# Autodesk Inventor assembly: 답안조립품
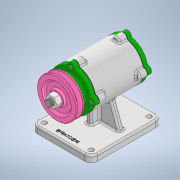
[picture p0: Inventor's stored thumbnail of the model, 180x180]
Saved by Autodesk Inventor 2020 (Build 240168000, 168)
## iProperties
Created: 2022-11
Part Number: 답안조립품
Document SubType Name: Assembly
Designer: owner
Author: owner
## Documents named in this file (12)
- C:\Users\owner\Desktop\721108V1016\답안조립품.iam
- C:\Users\owner\Desktop\721108V1016\본체.ipt
- C:\Users\owner\Desktop\721108V1016\V-벨트풀리.ipt
- C:\Users\owner\Desktop\721108V1016\개스킷.ipt
- C:\Users\owner\Desktop\721108V1016\너트 M12 x 1.25.ipt
- C:\Users\owner\Desktop\721108V1016\뒤커버.ipt
- C:\Users\owner\Desktop\721108V1016\베어링 6204.ipt
- C:\Users\owner\Desktop\721108V1016\볼트 M4 x 12.ipt
- C:\Users\owner\Desktop\721108V1016\앞커버.ipt
- C:\Users\owner\Desktop\721108V1016\오일 실.ipt
- C:\Users\owner\Desktop\721108V1016\축.ipt
- C:\Users\owner\Desktop\721108V1016\키 4 x 4.ipt
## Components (8 placed, 6 different names)
1. V-벨트풀리:1 — 각도:1
2. 개스킷:1
3. KS B 1012 클래스 1 일반 - 미터 M12x1.25:1 — 각도:1
4. KS B 2023 6204 - 20 x 47 x 14:1
5. KS B 2804 D D - 20 32 8:1
6. KS B 1311 (I) 4 x 4 x 12:1
7. KS B 2023 6204 - 20 x 47 x 14:2
8. 개스킷:2
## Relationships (1: Angle 1)
- 각도:1 [Angle]: V-벨트풀리:1 ↔ KS B 1012 클래스 1 일반 - 미터 M12x1.25:1
